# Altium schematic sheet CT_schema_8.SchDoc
size 277 x 170 mm
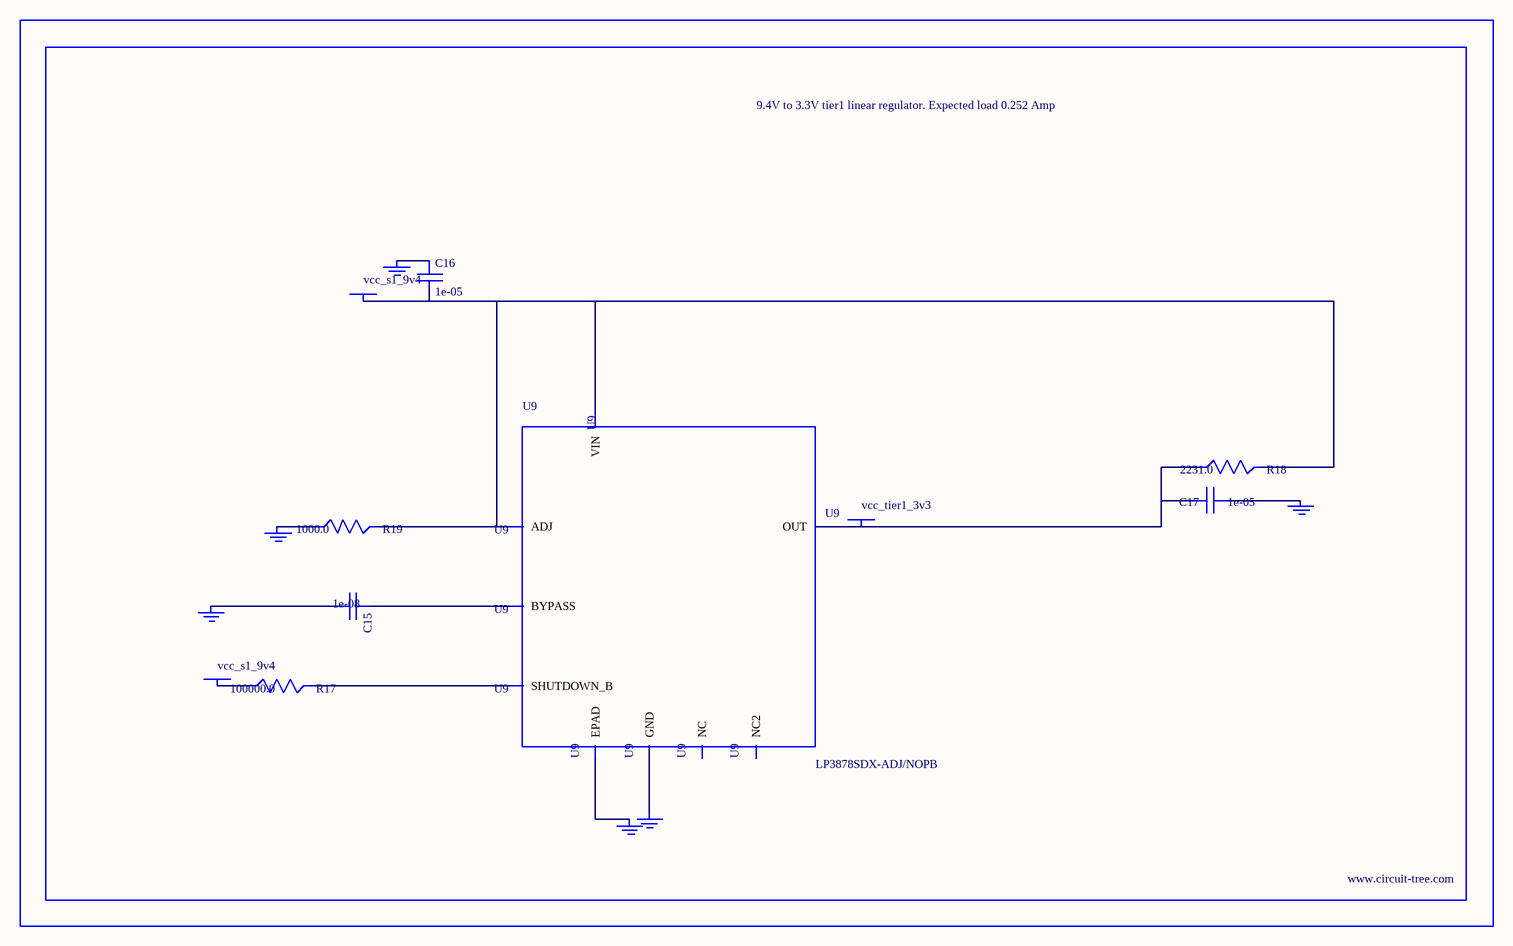
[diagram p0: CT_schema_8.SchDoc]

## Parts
BORDER7  (no value)
C15  1e-08  [C0402]
C16  1e-05  [C1206]
C17  1e-05  [C1210]
GND_INSTANCE_7_0  (no value)
GND_INSTANCE_7_1  (no value)
GND_INSTANCE_7_2  (no value)
GND_INSTANCE_7_3  (no value)
GND_INSTANCE_7_4  (no value)
GND_INSTANCE_7_5  (no value)
POWER_INSTANCE_7_0  vcc_s1_9v4
POWER_INSTANCE_7_1  vcc_s1_9v4
POWER_INSTANCE_7_2  vcc_tier1_3v3
R17  100000.0  [R0603]
R18  2231.0  [R0603]
R19  1000.0  [R0603]
U9  LP3878SDX-ADJ/NOPB  [WSON-8]

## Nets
NetC15_1: C15.1 U9.1(BYPASS)
NetC15_2: C15.2 GND_INSTANCE_7_0.0(GND)
NetC16_1: C16.1 GND_INSTANCE_7_1.0(GND)
NetC16_2: C16.2 POWER_INSTANCE_7_0.0(PWR) R18.2 R19.2 U9.4(VIN) U9.6(ADJ)
NetC17_1: C17.1 GND_INSTANCE_7_2.0(GND)
NetC17_2: C17.2 POWER_INSTANCE_7_2.0(PWR) R18.1 U9.5(OUT)
NetGND_INSTANCE_7_3_0: GND_INSTANCE_7_3.0(GND) R19.1
NetGND_INSTANCE_7_4_0: GND_INSTANCE_7_4.0(GND) U9.PAD(EPAD)
NetGND_INSTANCE_7_5_0: GND_INSTANCE_7_5.0(GND) U9.3(GND)
NetPOWER_INSTANCE_7_1_0: POWER_INSTANCE_7_1.0(PWR) R17.1
NetR17_2: R17.2 U9.8(SHUTDOWN_B)

Not connected (* = marked no-connect by the designer): U9 2(NC) 7(NC2)

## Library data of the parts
BORDER7 = BORDER_PAGE7
C15 = C0402C103K3RAC
C16 = C1206C106K3RACTU
C17 = GRM32DR61E106MA12L
GND_INSTANCE_7_0-GND_INSTANCE_7_5 = GND
POWER_INSTANCE_7_0-POWER_INSTANCE_7_2 = PWR
R17 = RC0603JR-07100KL
R18 = R18
R19 = RC0603JR-071KL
